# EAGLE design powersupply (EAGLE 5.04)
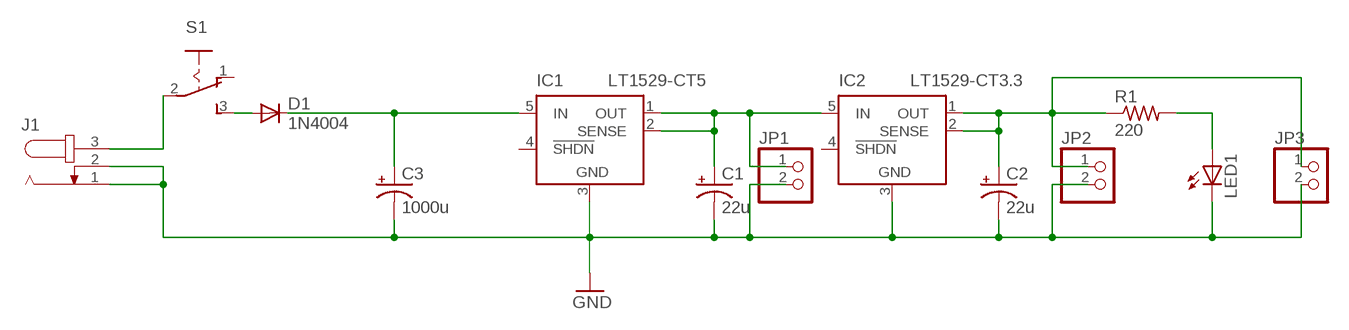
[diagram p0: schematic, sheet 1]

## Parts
C1  22u  CPOL-USE2.5-6  [E2,5-6]
C2  22u  CPOL-USE2.5-6  [E2,5-6]
C3  1000u  CPOL-USE3.5-8  [E3,5-8]
D1  1N4004  [DO41-10]
IC1  LT1529-CT5  LT1529-3.3T  [TO220-5]
IC2  LT1529-CT3.3  LT1529-3.3T  [TO220-5]
J1  JACK-PLUG0  [SPC4077]
JP1  PINHD-1X2  [1X02]
JP2  PINHD-1X2  [1X02]
JP3  PINHD-1X2  [1X02]
LED1  LED3MM  [LED3MM]
R1  220  R-US_0207/12  [0207/12]
S1  M251  [M251]

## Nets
GND: C1.- C2.- C3.- IC1.3(GND) IC2.3(GND) J1.1 J1.2 JP1.2 JP2.2 JP3.2 LED1.K(C)
N$1: C1.+ IC1.1(OUT) IC1.2(SENSE) IC2.5(IN) JP1.1
N$2: C2.+ IC2.1(OUT) IC2.2(SENSE) JP2.1 JP3.1 R1.1
N$3: C3.+ D1.C IC1.5(IN)
N$5: LED1.A R1.2
N$7: D1.A S1.3(S)
N$8: J1.3 S1.2(P)
Unconnected: IC1.4(!SHDN) IC2.4(!SHDN) S1.1(O)

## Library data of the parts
C1-C3 = rcl:CPOL-US: POLARIZED CAPACITOR, American symbol
D1 = diode:1N4004: DIODE
IC1 IC2 = linear-technology:LT1529: 1.5A, Low Noise, Fast Transient Response LDO Regulator Source: http://www.linear.com/pc/downloadDocument.do?navId=H0,C3,P2222,D3148
J1 = con-jack:JACK-PLUG: DC POWER JACK Power Jack, DC, Right Angle, Through Hole, Rated 5A at 16VDC, PC Terminals Distributor: Farnell (www.Farnell.de) Drawing: 84N1161.pdf / 84N1162.pdf Manufacturer: SPC Technology (www.spctechnology.com) Type: SPC4077 / SPC 4078
JP1-JP3 = pinhead:PINHD-1X2: PIN HEADER
LED1 = led:LED: LED
R1 = rcl:R-US_: RESISTOR, American symbol
S1 = switch:M251: SLIDING SWITCH Mors, distributor Buerklin, 11G702

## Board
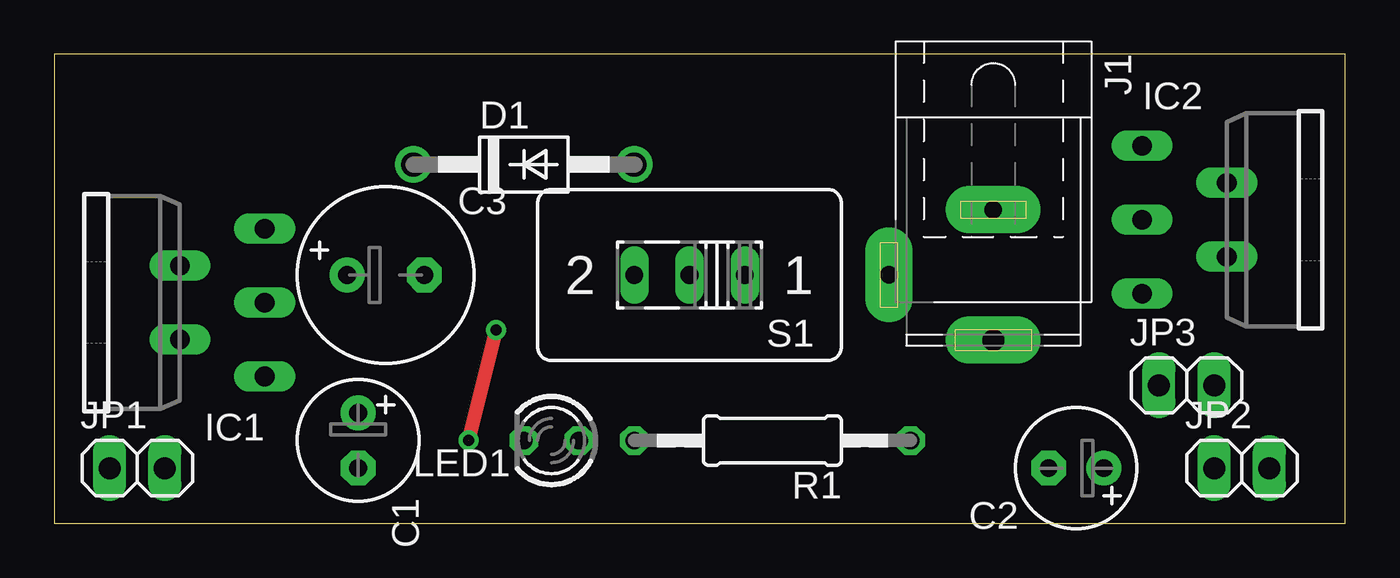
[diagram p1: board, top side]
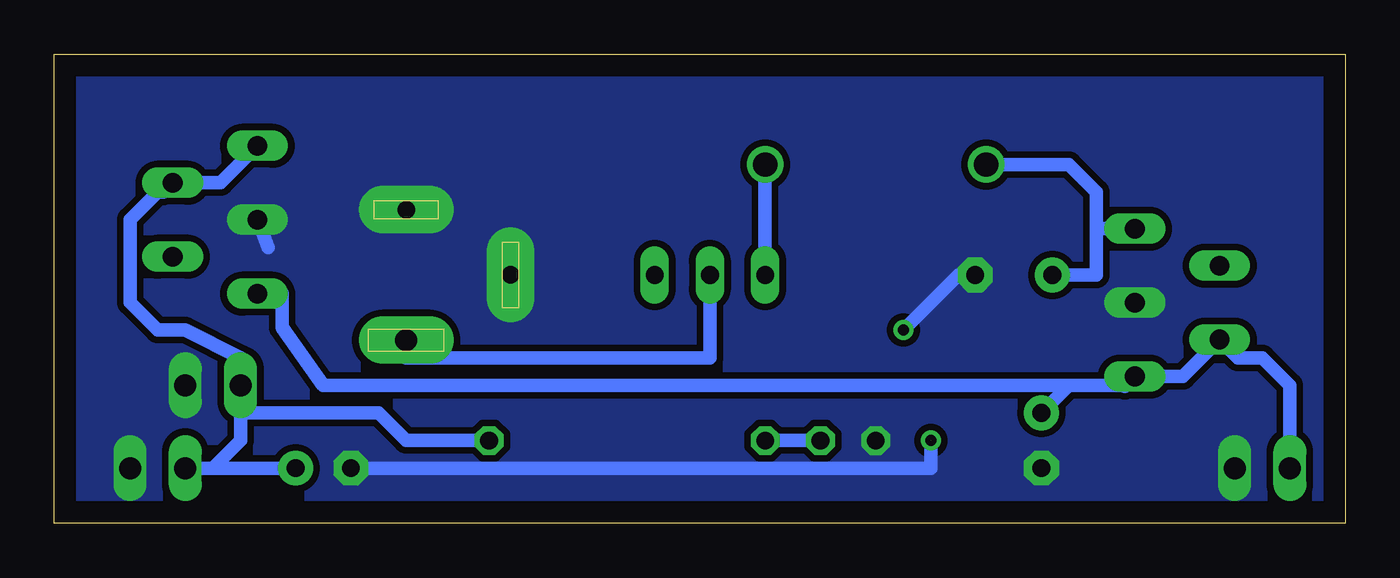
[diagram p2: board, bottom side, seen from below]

Size 59.36 x 21.58 mm. Coordinates in mm from the lower left corner, seen from the top.
Outline: 0,0 59.36,0 59.36,21.58 0,21.58 0,0
Copper layers (1*16): Top 0.035mm / dielectric 1.5mm / Bottom 0.035mm
Design rules "default": minimum track width 10mil, minimum drill 24mil, track to track 8mil, track to pad 8mil, pad to pad 8mil, via to via 8mil, smd to smd 8mil, copper to edge 40mil, drill to drill 8mil, minimum pad ring 10mil, minimum via ring 8mil, stop-mask expansion 4mil, vias tented up to drill 0mil, thermal gap 10mil

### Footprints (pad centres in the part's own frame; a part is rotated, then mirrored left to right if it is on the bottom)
E2,5-6 = drill 0.813 pad 1.6 round: + -1.27,0 | drill 0.813 pad 1.6 octagon: - 1.27,0
E3,5-8 = drill 0.813 pad 1.6 round: + -1.778,0 | drill 0.813 pad 1.6 octagon: - 1.778,0
DO41-10 = drill 1.118 round: A 5.08,0; C -5.08,0
TO220-5 = drill 0.9 long: 1 -3.4,-8.4; 2 -1.7,-4.5; 3 0,-8.4; 4 1.7,-4.5; 5 3.4,-8.4
SPC4077 = drill 0.8 pad 2.184 long: 1 -3,0; 2 0,-4.8 | drill 1 pad 2.184 long: 3 3,0
1X02 = drill 1.016 long: 1 -1.27,0; 2 1.27,0
LED3MM = drill 0.813 octagon: A -1.27,0; K 1.27,0
0207/12 = drill 0.813 octagon: 1 -6.35,0; 2 6.35,0
M251 = drill 0.813 long: 1 -2.54,0; 2 0,0; 3 2.54,0

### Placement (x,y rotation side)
C1  13.97,3.81 270 top
C2  46.99,2.54 180 top
C3  15.24,11.43 0 top
D1  21.59,16.51 0 top
IC1  1.27,10.16 90 top
IC2  58.42,13.97 270 top
J1  43.18,11.43 270 top
JP1  3.81,2.54 0 top
JP2  54.61,2.54 0 top
JP3  52.07,6.35 0 top
LED1  22.86,3.81 180 top
R1  33.02,3.81 180 top
S1  29.21,11.43 180 top

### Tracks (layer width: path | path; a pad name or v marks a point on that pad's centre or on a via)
GND  (via drill 0.51)  (1 unrouted)
  Top 0.61: v20.32,8.89 19.05,3.81
  Bottom 0.61: IC2.3 49.53,12.7 | C2.- 19.05,2.54 19.05,3.81 | 16.51,11.43 C3.- 17.78,11.43 v20.32,8.89
  pour Bottom (isolate 0.305, no thermals): -1.27,-1.27 60.96,-1.27 60.96,22.86 -1.27,22.86
N$1
  Bottom 0.61: JP1.1 2.54,6.35 3.81,7.62 4.93,7.62 IC1.2 7.47,6.76 IC1.1 10.12,6.31 10.16,6.35 12.7,6.35 | IC2.5 48.9,10.57 48.9,9.02 46.99,6.35 12.7,6.35 | 12.7,6.35 C1.+
N$2
  Bottom 0.61: 50.8,5.08 50.8,3.81 52.07,2.54 | 50.8,5.08 JP3.1 50.8,7.62 53.34,8.89 54.61,8.89 55.88,10.16 55.88,13.97 54.61,15.24 54.35,15.24 IC2.2 51.72,15.67 IC2.1 | 52.07,2.54 JP2.1 | R1.1 43.18,3.81 44.45,5.08 50.8,5.08 | 52.07,2.54 C2.+
N$3
  Bottom 0.61: IC1.5 11.43,13.56 | 11.43,13.56 11.43,11.43 C3.+ | 11.43,13.56 11.43,15.24 12.7,16.51 D1.C
N$4  (via drill 0.51)
  other vias: 19.05,3.81
N$5
  Bottom 0.61: LED1.A R1.2
N$6  (via drill 0.51)
  other vias: 20.32,8.89
N$7
  Bottom 0.61: S1.3 D1.A
N$8
  Bottom 0.61: J1.3 43.18,7.62 29.21,7.62 S1.2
